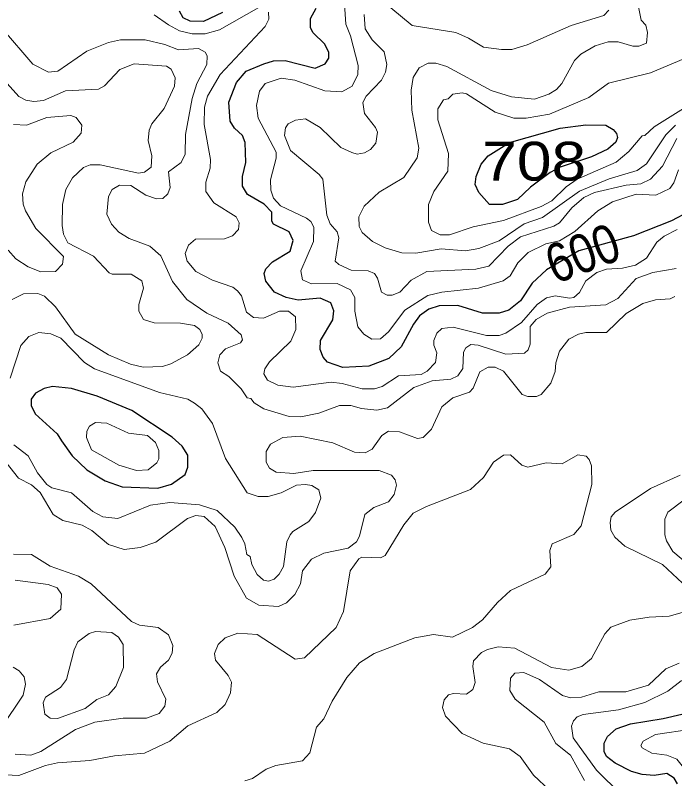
# Model space of a CAD drawing. Extents: x 577 to 602.9, y 7483.8 to 7511.6.
# Drawn here: x 589.958 to 591.318, y 7492.363 to 7493.938 of the extents above; entities that cross this region are included whole.
import ezdxf
from ezdxf.enums import TextEntityAlignment as Align

# ---------------------------------------------------------------- set-up
doc = ezdxf.new("R2010")
doc.units = 0
doc.header["$LTSCALE"] = 0.032
doc.layers.add('1', color=7, linetype='Continuous', lineweight=25)
doc.layers.add('2', color=7, linetype='Continuous', lineweight=13)
doc.layers.add('61', color=7, linetype='Continuous')

msp = doc.modelspace()

# ---------------------------------------------------------------- linework, layer by layer
at = {"layer": '1'}
for points in [[(591.3476, 7493.5334), (591.311, 7493.5143), (591.2331, 7493.4833), (591.1205, 7493.4519), (591.0534, 7493.4133), (591.024, 7493.3855), (591.0001, 7493.3489), (590.9755, 7493.3298), (590.9556, 7493.3235), (590.9214, 7493.3235), (590.8705, 7493.3394), (590.8323, 7493.3386), (590.8109, 7493.3322), (590.7918, 7493.3179), (590.7791, 7493.3012), (590.7536, 7493.2543), (590.7282, 7493.2304), (590.6868, 7493.2145), (590.6335, 7493.2114), (590.6017, 7493.2225), (590.593, 7493.2328), (590.5866, 7493.2487), (590.5874, 7493.267), (590.6129, 7493.31), (590.6153, 7493.3282), (590.6089, 7493.3449), (590.5866, 7493.3545), (590.5413, 7493.3505), (590.5167, 7493.3561), (590.4928, 7493.3672), (590.4745, 7493.3895), (590.4713, 7493.4054), (590.4745, 7493.4149), (590.4888, 7493.4292), (590.5246, 7493.4515), (590.531, 7493.4738), (590.523, 7493.4913), (590.4904, 7493.5072), (590.4872, 7493.5135), (590.4872, 7493.5318), (590.4713, 7493.5485), (590.4371, 7493.5684), (590.4268, 7493.5859), (590.4268, 7493.6058), (590.4332, 7493.6344), (590.4324, 7493.6757), (590.4268, 7493.6901), (590.4101, 7493.7052), (590.4014, 7493.7195), (590.3982, 7493.7592), (590.4141, 7493.7998), (590.434, 7493.8228), (590.4705, 7493.838), (590.4904, 7493.8443), (590.5143, 7493.8451), (590.5763, 7493.8292), (590.597, 7493.838), (590.6049, 7493.8499), (590.6049, 7493.861), (590.5962, 7493.8785), (590.5715, 7493.9024), (590.5668, 7493.9127), (590.5668, 7493.9318), (590.5787, 7493.9525)], [(590.3855, 7493.9437), (590.3465, 7493.9254), (590.3187, 7493.9262), (590.3043, 7493.9326), (590.2964, 7493.9469)], [(591.3238, 7492.3526), (591.3166, 7492.3645), (591.3015, 7492.374), (591.2753, 7492.3701), (591.2506, 7492.3717), (591.2291, 7492.378), (591.1949, 7492.3955), (591.1774, 7492.409), (591.1727, 7492.4194), (591.1727, 7492.4369), (591.179, 7492.4504), (591.1973, 7492.4663), (591.2267, 7492.4766), (591.2943, 7492.4877), (591.4391, 7492.5211)]]:
    msp.add_lwpolyline(points, dxfattribs=at)
for points in [[(590.9773, 7493.6756), (591.082, 7493.7052), (591.1345, 7493.7123), (591.1759, 7493.7115), (591.191, 7493.7028), (591.1981, 7493.694), (591.1997, 7493.6861), (591.1965, 7493.6765), (591.1798, 7493.6622), (591.1464, 7493.6463), (591.082, 7493.6248), (591.0614, 7493.6137), (591.0208, 7493.5835), (590.9935, 7493.5584), (590.9626, 7493.5479), (590.9358, 7493.5479), (590.9139, 7493.5723), (590.9066, 7493.5894), (590.9087, 7493.6058), (590.919, 7493.6312), (590.9333, 7493.6479)], [(590.0537, 7493.0603), (590.0753, 7493.0293), (590.1056, 7493.0006), (590.1437, 7492.9776), (590.1787, 7492.9656), (590.2519, 7492.9625), (590.2805, 7492.9712), (590.3083, 7492.9911), (590.3139, 7493.0062), (590.3139, 7493.0309), (590.302, 7493.0491), (590.2813, 7493.0682), (590.1986, 7493.1231), (590.127, 7493.1525), (590.0737, 7493.1684), (590.0348, 7493.1724), (590.0173, 7493.1684), (589.9998, 7493.1589), (589.991, 7493.1462), (589.991, 7493.1334), (589.999, 7493.1159), (590.0443, 7493.0746)]]:
    msp.add_lwpolyline(points, close=True, dxfattribs=at)
at = {"layer": '2'}
for points in [[(590.4602, 7493.9541), (590.3791, 7493.9079), (590.3497, 7493.9), (590.3226, 7493.9), (590.2964, 7493.9063), (590.2741, 7493.9183), (590.2447, 7493.9389)], [(590.6367, 7493.9612), (590.6399, 7493.9199), (590.6495, 7493.896), (590.6654, 7493.8348), (590.6646, 7493.8157), (590.6526, 7493.7918), (590.6312, 7493.7799), (590.5962, 7493.7823), (590.5342, 7493.8046), (590.5063, 7493.8085), (590.4737, 7493.7974)], [(590.7322, 7493.9533), (590.7767, 7493.9167), (590.8665, 7493.9024), (590.8928, 7493.8912), (590.9238, 7493.8721), (590.9604, 7493.8674), (590.9818, 7493.8674), (591.0136, 7493.8769), (591.1043, 7493.9167), (591.1719, 7493.9374), (591.1822, 7493.9485)], [(591.2427, 7493.9588), (591.249, 7493.9278), (591.2586, 7493.9175), (591.2617, 7493.9024), (591.2594, 7493.8809), (591.2442, 7493.8745), (591.2315, 7493.8745), (591.2013, 7493.8833), (591.1806, 7493.8833), (591.1536, 7493.8753), (591.1242, 7493.8578), (591.1114, 7493.8451), (591.0852, 7493.7974), (591.0741, 7493.7847), (591.0582, 7493.7751), (591.0288, 7493.7648), (590.981, 7493.7696), (590.9397, 7493.7831), (590.8482, 7493.8324), (590.8252, 7493.8395), (590.8093, 7493.8395), (590.791, 7493.83)], [(590.4705, 7493.1986), (590.4729, 7493.209), (590.4825, 7493.2233), (590.5262, 7493.2662), (590.5365, 7493.2901), (590.5357, 7493.3163), (590.5214, 7493.3275), (590.5031, 7493.3275), (590.4697, 7493.3131), (590.4491, 7493.3147), (590.4348, 7493.3259), (590.4244, 7493.3593), (590.4165, 7493.3696), (590.4069, 7493.3775), (590.3648, 7493.3919), (590.3306, 7493.4094), (590.3123, 7493.4308), (590.3083, 7493.4467), (590.3155, 7493.4642), (590.3298, 7493.4761), (590.3894, 7493.4769), (590.4061, 7493.4833), (590.4181, 7493.496), (590.4196, 7493.5103), (590.4133, 7493.5223), (590.3672, 7493.5509), (590.3513, 7493.5748), (590.3513, 7493.5938), (590.36, 7493.6225), (590.3608, 7493.6408), (590.3473, 7493.7131), (590.3481, 7493.7489), (590.3544, 7493.7712), (590.3807, 7493.8157), (590.4737, 7493.9151), (590.4809, 7493.9302), (590.4801, 7493.9445)], [(591.3222, 7493.6837), (591.2927, 7493.6272), (591.2681, 7493.6002), (591.2482, 7493.5907), (591.218, 7493.5875), (591.1528, 7493.5724), (591.1305, 7493.562), (591.1059, 7493.5406), (591.0804, 7493.5103), (591.0685, 7493.5032), (591.0001, 7493.4809), (590.9747, 7493.4618), (590.9349, 7493.4205), (590.9079, 7493.4141), (590.8069, 7493.4094), (590.7743, 7493.3919), (590.7512, 7493.3672), (590.7353, 7493.3608), (590.725, 7493.3608), (590.7131, 7493.3672), (590.7051, 7493.3958), (590.6988, 7493.4054), (590.686, 7493.4109), (590.651, 7493.4125), (590.6256, 7493.4237), (590.6176, 7493.4308), (590.6256, 7493.4793), (590.6216, 7493.4913), (590.6073, 7493.508), (590.6002, 7493.5255), (590.5922, 7493.6002), (590.585, 7493.6097), (590.5254, 7493.659), (590.5135, 7493.6901), (590.5151, 7493.706), (590.5206, 7493.7139), (590.5357, 7493.7219), (590.5564, 7493.7242), (590.5866, 7493.7068), (590.6296, 7493.6654), (590.6518, 7493.6551), (590.663, 7493.6519), (590.6781, 7493.6543), (590.6908, 7493.6614), (590.7019, 7493.6741), (590.7051, 7493.6972), (590.7011, 7493.7068), (590.6781, 7493.7354), (590.6749, 7493.7584), (590.6813, 7493.7712), (590.7131, 7493.8046), (590.7218, 7493.8205), (590.7242, 7493.8364), (590.7186, 7493.8626), (590.694, 7493.8873), (590.6797, 7493.9103), (590.6773, 7493.9397)], [(590.4268, 7493.2686), (590.4236, 7493.2789), (590.3974, 7493.3028), (590.3529, 7493.3235), (590.3115, 7493.3521), (590.2821, 7493.3887), (590.2582, 7493.442), (590.2352, 7493.4618), (590.193, 7493.4777), (590.1716, 7493.4905), (590.1564, 7493.5072), (590.1469, 7493.5278), (590.1501, 7493.5644), (590.158, 7493.5787), (590.1731, 7493.5875), (590.1962, 7493.5867), (590.2272, 7493.5668), (590.2495, 7493.5596), (590.2622, 7493.5604), (590.2725, 7493.57), (590.2773, 7493.5827), (590.2741, 7493.6153), (590.3004, 7493.6344), (590.3083, 7493.6519), (590.3091, 7493.6924), (590.3226, 7493.7664), (590.3322, 7493.7974), (590.3529, 7493.8364), (590.3536, 7493.8547), (590.3497, 7493.8618), (590.3362, 7493.8698), (590.2948, 7493.8666), (590.2662, 7493.8777), (590.2256, 7493.8873), (590.1747, 7493.8873), (590.1501, 7493.8817), (590.1056, 7493.8642), (590.0459, 7493.8228), (590.0268, 7493.8205), (589.9942, 7493.8372), (589.9314, 7493.9103)], [(591.3365, 7493.8483), (591.2681, 7493.8197), (591.1814, 7493.7982), (591.1409, 7493.7688), (591.0598, 7493.7338), (591.0113, 7493.7258), (590.9858, 7493.7258), (590.9476, 7493.7386), (590.8888, 7493.7759), (590.8793, 7493.7783), (590.8602, 7493.7751), (590.8506, 7493.7656), (590.8411, 7493.764), (590.8292, 7493.7449), (590.8292, 7493.7227), (590.8514, 7493.6527), (590.8498, 7493.6165), (590.8212, 7493.5748), (590.8101, 7493.5477), (590.8101, 7493.5111), (590.8164, 7493.4944), (590.8339, 7493.4849), (590.8538, 7493.4849), (590.9023, 7493.5016), (590.9651, 7493.5151), (591.0423, 7493.5437), (591.0645, 7493.5557), (591.094, 7493.5843), (591.117, 7493.6002), (591.1973, 7493.6352), (591.2236, 7493.6574), (591.2506, 7493.6893), (591.2562, 7493.6901), (591.2753, 7493.7083), (591.3802, 7493.7735)], [(589.9163, 7493.8244), (589.9656, 7493.7704), (589.9799, 7493.7632), (589.9966, 7493.76), (590.0165, 7493.7624), (590.0618, 7493.7823), (590.1294, 7493.7855), (590.1421, 7493.7926), (590.1739, 7493.826), (590.2034, 7493.838)], [(590.2034, 7493.838), (590.2702, 7493.8332), (590.2797, 7493.8268), (590.2876, 7493.8093), (590.2861, 7493.7918), (590.2654, 7493.7457), (590.2399, 7493.7139), (590.2344, 7493.7012), (590.232, 7493.6797), (590.2399, 7493.6479), (590.2383, 7493.6248), (590.2248, 7493.6145), (590.2121, 7493.6121), (590.1334, 7493.6296), (590.1127, 7493.6296), (590.0984, 7493.6241), (590.0761, 7493.6026), (590.0626, 7493.5787), (590.0555, 7493.5477), (590.0547, 7493.5048), (590.0578, 7493.4865), (590.0666, 7493.469), (590.1191, 7493.4412), (590.1517, 7493.407), (590.158, 7493.4038), (590.197, 7493.4038), (590.2193, 7493.3903), (590.2224, 7493.3752), (590.2129, 7493.3418), (590.2129, 7493.3275), (590.2224, 7493.3108), (590.2447, 7493.3036), (590.2988, 7493.3028), (590.3274, 7493.298), (590.3385, 7493.2901), (590.3433, 7493.2797), (590.3433, 7493.2718), (590.3369, 7493.2583), (590.3131, 7493.2376), (590.2789, 7493.2193), (590.2614, 7493.2137), (590.2216, 7493.2122), (590.1954, 7493.2185), (590.1501, 7493.2376), (590.0817, 7493.2805), (590.0411, 7493.337), (590.0181, 7493.3585), (590.0046, 7493.364), (589.9751, 7493.3632), (589.9513, 7493.3521)], [(590.791, 7493.83), (590.7783, 7493.8101), (590.7743, 7493.7839), (590.7759, 7493.7425), (590.7902, 7493.6638), (590.787, 7493.6439), (590.7592, 7493.6034), (590.7083, 7493.5732), (590.6773, 7493.5445), (590.6662, 7493.5223), (590.6669, 7493.5024), (590.6733, 7493.4897), (590.6948, 7493.4714), (590.721, 7493.4587), (590.7552, 7493.4483), (590.7838, 7493.4475), (590.8363, 7493.4563), (590.8864, 7493.4523), (590.9142, 7493.4571), (590.9556, 7493.473), (591.0073, 7493.508), (591.0454, 7493.5207), (591.1218, 7493.5755), (591.183, 7493.601), (591.2403, 7493.6177), (591.2594, 7493.632), (591.2999, 7493.6916), (591.3198, 7493.7115)], [(590.4737, 7493.7974), (590.4618, 7493.7815), (590.4554, 7493.7521), (590.4586, 7493.7258), (590.496, 7493.6559), (590.496, 7493.6431), (590.4841, 7493.5986), (590.4849, 7493.5771), (590.4904, 7493.5612), (590.5047, 7493.5453), (590.5588, 7493.5199), (590.5675, 7493.5127), (590.5739, 7493.5008), (590.5731, 7493.4714), (590.5469, 7493.4109), (590.5501, 7493.3927), (590.5691, 7493.3839), (590.6216, 7493.3847), (590.6495, 7493.372), (590.6582, 7493.3561), (590.6582, 7493.3275), (590.6646, 7493.2956), (590.6765, 7493.2805), (590.6932, 7493.2702), (590.7115, 7493.271), (590.7274, 7493.2853), (590.7616, 7493.3298), (590.8085, 7493.3601), (590.8379, 7493.3672), (590.9135, 7493.3752), (590.9643, 7493.3903), (590.9787, 7493.4006), (590.9946, 7493.4276), (591.016, 7493.4491), (591.0518, 7493.4666), (591.0804, 7493.473)], [(589.9545, 7493.7131), (589.9815, 7493.7115), (590.0229, 7493.7274), (590.0729, 7493.7314), (590.0833, 7493.7274), (590.0952, 7493.7115), (590.0936, 7493.6948), (590.0777, 7493.6765), (590.0316, 7493.6543), (590.003, 7493.6312), (589.9799, 7493.5946), (589.9728, 7493.57), (589.9743, 7493.5485), (589.9791, 7493.535), (590.0006, 7493.4984), (590.0578, 7493.4404), (590.0555, 7493.4245), (590.0411, 7493.4094), (590.0109, 7493.4086), (589.9847, 7493.4189), (589.9592, 7493.4356), (589.9433, 7493.4539)], [(591.0804, 7493.473), (591.1122, 7493.4921), (591.1592, 7493.535), (591.1894, 7493.5533), (591.2387, 7493.5692), (591.2792, 7493.5668), (591.3079, 7493.5811), (591.3158, 7493.5922), (591.3254, 7493.6193)], [(591.323, 7493.496), (591.2959, 7493.4825), (591.2808, 7493.4698), (591.2594, 7493.4372), (591.2371, 7493.4229), (591.2101, 7493.4165), (591.1774, 7493.4141), (591.1576, 7493.4078), (591.1345, 7493.3903), (591.1218, 7493.3664), (591.1099, 7493.3561), (591.1011, 7493.3545), (591.0717, 7493.3593), (591.0534, 7493.3553), (591.0343, 7493.3418), (591.0017, 7493.3044), (590.9699, 7493.2821), (590.9556, 7493.2774), (590.9301, 7493.2774), (590.861, 7493.2948), (590.8379, 7493.2917), (590.8276, 7493.2821), (590.8212, 7493.267), (590.8212, 7493.2575), (590.8276, 7493.2416), (590.8244, 7493.2217), (590.8077, 7493.2042), (590.795, 7493.197), (590.7481, 7493.1947), (590.7147, 7493.1724), (590.6988, 7493.1676), (590.6733, 7493.1676), (590.632, 7493.1788), (590.6097, 7493.1811), (590.531, 7493.1708), (590.4992, 7493.1748), (590.4785, 7493.1851), (590.4705, 7493.1986)], [(591.3206, 7493.4157), (591.2729, 7493.4078), (591.2387, 7493.395), (591.2005, 7493.3537), (591.1759, 7493.341), (591.1011, 7493.3362), (591.055, 7493.3235), (591.0319, 7493.3108), (591.02, 7493.2964), (591.02, 7493.2599), (591.016, 7493.2479), (591.0081, 7493.2408), (590.9699, 7493.2392), (590.9127, 7493.2575), (590.8975, 7493.2591), (590.8872, 7493.2519), (590.8824, 7493.2432), (590.8808, 7493.2098), (590.8705, 7493.1947), (590.8562, 7493.1875), (590.818, 7493.1843), (590.7799, 7493.17), (590.7258, 7493.1287), (590.7035, 7493.1239), (590.6717, 7493.1271), (590.6502, 7493.1334), (590.6264, 7493.1334), (590.5842, 7493.1175), (590.5469, 7493.1096), (590.523, 7493.1104), (590.4705, 7493.1263), (590.4507, 7493.139), (590.4435, 7493.1477), (590.4363, 7493.1493), (590.4236, 7493.1676), (590.3982, 7493.1931), (590.3815, 7493.2042), (590.3759, 7493.2209), (590.3799, 7493.2376), (590.3918, 7493.2503), (590.4228, 7493.2622), (590.4268, 7493.2686)], [(590.4753, 7493.0165), (590.4753, 7493.038), (590.4841, 7493.0531), (590.5095, 7493.0674), (590.5453, 7493.0698), (590.6129, 7493.0563), (590.6574, 7493.0372), (590.6797, 7493.0356), (590.694, 7493.0428), (590.7139, 7493.0714), (590.7274, 7493.0802), (590.7504, 7493.0786), (590.7878, 7493.065), (590.7989, 7493.0674), (590.8164, 7493.0841), (590.8379, 7493.1302), (590.8602, 7493.1493), (590.8944, 7493.1605), (590.9023, 7493.1692), (590.9158, 7493.2026), (590.9333, 7493.2122), (590.9476, 7493.2122), (590.9651, 7493.2042), (591.0033, 7493.1557), (591.0152, 7493.1517), (591.0327, 7493.1517), (591.0423, 7493.1557), (591.0621, 7493.1795), (591.0717, 7493.2034), (591.0725, 7493.2209), (591.0804, 7493.2455), (591.0995, 7493.2702), (591.1194, 7493.2805), (591.1345, 7493.2837), (591.1774, 7493.2837), (591.218, 7493.3227), (591.2522, 7493.3434), (591.2784, 7493.3513), (591.3087, 7493.3529), (591.3182, 7493.3577)], [(589.9473, 7493.1899), (589.9696, 7493.2567), (589.9863, 7493.2758), (590.0069, 7493.2837), (590.0316, 7493.2813), (590.0523, 7493.2718), (590.1008, 7493.2217), (590.1215, 7493.209), (590.2558, 7493.1597), (590.3139, 7493.1462), (590.3274, 7493.1382), (590.3425, 7493.1263), (590.3648, 7493.0961), (590.3918, 7493.0237), (590.4363, 7492.9529), (590.4586, 7492.9458), (590.4793, 7492.9458), (590.5063, 7492.9529), (590.5381, 7492.9688), (590.5564, 7492.9704), (590.5699, 7492.968), (590.5842, 7492.9593), (590.5882, 7492.9418), (590.5771, 7492.9124), (590.5636, 7492.8941), (590.5302, 7492.8734), (590.5246, 7492.8662), (590.5182, 7492.8519), (590.5111, 7492.801), (590.5023, 7492.7851), (590.492, 7492.7748), (590.4801, 7492.7708), (590.4697, 7492.7732), (590.457, 7492.7843), (590.4459, 7492.805), (590.4427, 7492.8217), (590.4355, 7492.8257), (590.4316, 7492.848), (590.4252, 7492.8607), (590.4109, 7492.8822), (590.3743, 7492.9163), (590.3377, 7492.9283), (590.2765, 7492.933), (590.2368, 7492.9275), (590.1692, 7492.9004), (590.1389, 7492.9036), (590.1183, 7492.9148), (590.0737, 7492.9529), (590.0332, 7492.9633), (590.0229, 7492.9704), (590.0038, 7492.9943), (589.9847, 7493.0293), (589.9553, 7493.0523)], [(589.9179, 7493.042), (589.9648, 7492.9831), (589.9918, 7492.9696), (590.0093, 7492.9537), (590.0364, 7492.9084), (590.0563, 7492.8957), (590.096, 7492.8861), (590.1159, 7492.875), (590.1501, 7492.8464), (590.1827, 7492.836), (590.2153, 7492.84), (590.2479, 7492.8511), (590.3131, 7492.9004), (590.3306, 7492.906), (590.3473, 7492.9044), (590.3703, 7492.8837), (590.3902, 7492.84), (590.4093, 7492.7812), (590.4348, 7492.7358), (590.4602, 7492.7215), (590.5008, 7492.7183), (590.5175, 7492.7263), (590.5342, 7492.743), (590.5461, 7492.7653), (590.5501, 7492.7923), (590.5691, 7492.8162), (590.5946, 7492.8289), (590.6447, 7492.8392), (590.6614, 7492.8519), (590.6677, 7492.8639), (590.6789, 7492.9084), (590.6972, 7492.9227), (590.7274, 7492.9346), (590.7393, 7492.9497), (590.7441, 7492.9688), (590.7417, 7492.98), (590.7337, 7492.9895), (590.7083, 7492.999), (590.5723, 7492.999), (590.5326, 7492.9927), (590.496, 7492.9959), (590.4825, 7493.0038), (590.4753, 7493.0165)], [(589.8972, 7492.3732), (589.9656, 7492.3701), (590.0205, 7492.3907), (590.0451, 7492.3963), (590.1119, 7492.4011), (590.1628, 7492.4106), (590.2248, 7492.4162), (590.2765, 7492.4408), (590.3139, 7492.4726), (590.3735, 7492.4997), (590.391, 7492.5164), (590.4022, 7492.5402), (590.4037, 7492.5625), (590.3974, 7492.576), (590.3711, 7492.6078), (590.3688, 7492.6213), (590.3767, 7492.6404), (590.391, 7492.6539), (590.4173, 7492.6635), (590.457, 7492.6611), (590.5349, 7492.6102), (590.5548, 7492.6126), (590.62, 7492.6754), (590.6351, 7492.708), (590.6487, 7492.7923), (590.6662, 7492.8169), (590.6725, 7492.8201), (590.7115, 7492.8193), (590.721, 7492.8241), (590.7592, 7492.8869), (590.7783, 7492.9108), (590.8061, 7492.9251), (590.8968, 7492.9601), (590.9238, 7492.9847), (590.9445, 7493.0165), (590.9651, 7493.0309), (590.9795, 7493.0316), (591.0025, 7493.0102), (591.0152, 7493.0062), (591.0526, 7493.0149), (591.086, 7493.0126), (591.1178, 7493.0316), (591.1353, 7493.0285), (591.1417, 7493.0221), (591.1464, 7493.0086), (591.1472, 7492.9704), (591.125, 7492.8853), (591.1099, 7492.867), (591.0653, 7492.848), (591.0606, 7492.8344), (591.0621, 7492.8003), (591.051, 7492.7851), (590.9795, 7492.7517), (590.9524, 7492.7271), (590.9214, 7492.6913), (590.9007, 7492.6754), (590.8594, 7492.6555), (590.8204, 7492.6611), (590.7822, 7492.6539)], [(591.3293, 7492.9895), (591.2681, 7492.9617), (591.1949, 7492.9132), (591.187, 7492.9036), (591.1846, 7492.8917), (591.1862, 7492.8758), (591.1941, 7492.8615), (591.2148, 7492.8432), (591.2927, 7492.805), (591.3444, 7492.7573)], [(591.3444, 7492.8066), (591.3142, 7492.8321), (591.3007, 7492.8543), (591.2975, 7492.8662), (591.2975, 7492.8989), (591.3039, 7492.9132), (591.4104, 7492.9935)], [(589.9545, 7492.8265), (589.9918, 7492.8257), (590.03, 7492.8018), (590.0881, 7492.7812), (590.1143, 7492.7653), (590.1978, 7492.6873), (590.2145, 7492.6802), (590.2527, 7492.6754), (590.2741, 7492.6603), (590.2829, 7492.638), (590.2813, 7492.6221), (590.2741, 7492.6078), (590.2574, 7492.5935), (590.2495, 7492.58), (590.2511, 7492.5633), (590.2686, 7492.5275), (590.2662, 7492.5132), (590.255, 7492.4981), (590.2288, 7492.4885), (590.1803, 7492.4885), (590.1223, 7492.4798), (590.0825, 7492.4647), (590.0109, 7492.4194), (589.9903, 7492.4122), (589.9576, 7492.4138)], [(591.3723, 7492.8241), (591.4351, 7492.7995), (591.4558, 7492.7859), (591.49, 7492.7207), (591.5273, 7492.6818), (591.5297, 7492.6683), (591.5265, 7492.6603), (591.5114, 7492.6492), (591.4812, 7492.6396), (591.4112, 7492.5967), (591.3309, 7492.5649), (591.3039, 7492.5442), (591.2562, 7492.5203), (591.2021, 7492.5052), (591.1289, 7492.4957), (591.117, 7492.4909), (591.1091, 7492.483), (591.1051, 7492.4718), (591.1083, 7492.448), (591.1568, 7492.3812), (591.2077, 7492.3311)], [(589.9553, 7492.6802), (590.03, 7492.6937), (590.0523, 7492.7128), (590.0531, 7492.7438), (590.0443, 7492.7573), (590.026, 7492.7637), (589.9576, 7492.7732)], [(591.3476, 7492.7104), (591.3063, 7492.6985), (591.2649, 7492.6969), (591.2252, 7492.6905), (591.1862, 7492.6762), (591.1735, 7492.6619), (591.1464, 7492.611), (591.1266, 7492.5951), (591.0995, 7492.5871), (591.0637, 7492.5927), (590.9882, 7492.6325), (590.954, 7492.6356), (590.9317, 7492.6301), (590.9198, 7492.6237), (590.9031, 7492.6062), (590.9015, 7492.5951), (590.9063, 7492.5617), (590.9015, 7492.5474), (590.8888, 7492.5378), (590.8618, 7492.5394), (590.8517, 7492.5364), (590.8428, 7492.5262), (590.839, 7492.5104), (590.8454, 7492.4926), (590.8793, 7492.4567), (590.923, 7492.4369), (590.9771, 7492.4249), (590.9993, 7492.409), (591.0264, 7492.3709), (591.0606, 7492.339)], [(590.7822, 7492.6539), (590.698, 7492.6213), (590.6677, 7492.6023), (590.6415, 7492.572), (590.6113, 7492.5235), (590.5946, 7492.487), (590.5795, 7492.4695), (590.5652, 7492.417), (590.5501, 7492.4003), (590.4952, 7492.3907), (590.4753, 7492.3828), (590.4475, 7492.3637), (590.4316, 7492.3589)], [(591.1321, 7492.3597), (591.1027, 7492.4122), (591.0725, 7492.4361), (591.0486, 7492.4798), (590.989, 7492.5275), (590.9779, 7492.545), (590.9795, 7492.5704), (590.9882, 7492.5808), (591.0065, 7492.5824), (591.0391, 7492.5681), (591.0868, 7492.5347), (591.1027, 7492.5299), (591.1258, 7492.5315), (591.1615, 7492.5426), (591.2172, 7492.5426), (591.2641, 7492.5561), (591.2999, 7492.5903), (591.3269, 7492.6015)], [(589.9298, 7492.4687), (589.9743, 7492.5355), (589.9791, 7492.5585), (589.9767, 7492.5736), (589.9664, 7492.5856), (589.9537, 7492.5935)]]:
    msp.add_lwpolyline(points, dxfattribs=at)
for points in [[(590.2471, 7493.0571), (590.2542, 7493.0404), (590.2542, 7493.0229), (590.2503, 7493.0149), (590.232, 7493.0006), (590.2081, 7492.999), (590.1716, 7493.0102), (590.1151, 7493.042), (590.1048, 7493.0674), (590.1056, 7493.0802), (590.1111, 7493.0905), (590.1238, 7493.0984), (590.1469, 7493.0969), (590.1914, 7493.0762), (590.2304, 7493.0714)], [(590.0793, 7492.6293), (590.0634, 7492.5681), (590.0515, 7492.5514), (590.0205, 7492.5315), (590.0157, 7492.5196), (590.0189, 7492.4965), (590.03, 7492.4885), (590.0451, 7492.4877), (590.1024, 7492.5084), (590.1262, 7492.5267), (590.1501, 7492.5363), (590.1652, 7492.5537), (590.1811, 7492.5927), (590.1803, 7492.6404), (590.1708, 7492.6555), (590.1572, 7492.6651), (590.1238, 7492.6667), (590.1103, 7492.6627), (590.0873, 7492.646)], [(591.3532, 7492.4655), (591.4176, 7492.4774), (591.4375, 7492.4742), (591.4478, 7492.4607), (591.4438, 7492.4456), (591.4271, 7492.4313), (591.4112, 7492.4241), (591.3937, 7492.4058), (591.381, 7492.3756), (591.3699, 7492.3701), (591.3595, 7492.3701), (591.3444, 7492.3764), (591.3222, 7492.4035), (591.3015, 7492.4122), (591.2705, 7492.4162), (591.2506, 7492.4273), (591.2482, 7492.4321), (591.253, 7492.4408), (591.2784, 7492.4543)]]:
    msp.add_lwpolyline(points, close=True, dxfattribs=at)

# ---------------------------------------------------------------- texts
at = {"layer": '61', "width": 1.2}
msp.add_text('708', height=0.08, dxfattribs=at).set_placement((591.0282, 7493.5972), align=Align.CENTER)
at = {"layer": '61', "width": 0.85}
msp.add_text('600', height=0.08, rotation=20.729, dxfattribs=at).set_placement((591.1421, 7493.4099), align=Align.CENTER)

doc.saveas('drawing.dxf')
